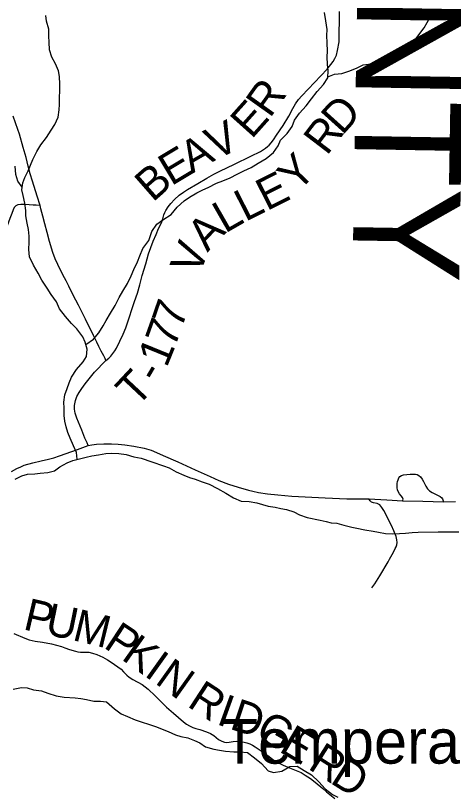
# Model space of a CAD drawing. Extents: x 0 to 34, y 0 to 22.
# Drawn here: x 26.05 to 26.826, y 17.051 to 18.434 of the extents above; entities that cross this region are included whole.
import ezdxf

# ---------------------------------------------------------------- set-up
doc = ezdxf.new("R2010")
doc.units = 0
for name, color, linetype in [('GM_X_County_Road', 7, 'Continuous'), ('GM_X_County_Text', 7, 'Continuous'), ('GM_X_Minor_River', 7, 'Continuous'), ('GM_X_Township_Road', 7, 'Continuous'), ('GM_X_Township_Road_Text', 7, 'Continuous'), ('GM_X_Unincorporated_Text', 7, 'Continuous')]:
    doc.layers.add(name, color=color, linetype=linetype)

msp = doc.modelspace()

# ---------------------------------------------------------------- linework, layer by layer
at = {"layer": 'GM_X_County_Road'}
msp.add_lwpolyline([(26.0424, 17.6262), (26.052, 17.6317), (26.0588, 17.6347), (26.0651, 17.6373), (26.0801, 17.6418), (26.0952, 17.6449), (26.1078, 17.6479), (26.1177, 17.6507), (26.1276, 17.6538), (26.1594, 17.665), (26.1783, 17.6721), (26.1851, 17.6732), (26.1934, 17.6744), (26.206, 17.6755), (26.2198, 17.675), (26.2317, 17.6744), (26.2435, 17.6734), (26.2594, 17.6713), (26.2779, 17.6678), (26.2902, 17.6639), (26.2998, 17.66), (26.3117, 17.6548), (26.3373, 17.6432), (26.3681, 17.6289), (26.3946, 17.6173), (26.4104, 17.6103), (26.4274, 17.6039), (26.4444, 17.5985), (26.4629, 17.5934), (26.4702, 17.5916), (26.4803, 17.5893), (26.4962, 17.5868), (26.5147, 17.5848), (26.5399, 17.5827), (26.5986, 17.5798), (26.6372, 17.5779), (26.6762, 17.5777), (26.7082, 17.5761), (26.7362, 17.5744), (26.7722, 17.5734), (26.8085, 17.5727), (26.8297, 17.5731)], dxfattribs=at)
at = {"layer": 'GM_X_Minor_River'}
for points in [[(26.286, 18.0353), (26.2913, 18.0514), (26.3002, 18.0644), (26.3107, 18.0721), (26.3254, 18.0818), (26.3362, 18.0948), (26.3485, 18.1056), (26.3583, 18.1122), (26.371, 18.1199), (26.3816, 18.125), (26.3913, 18.1293), (26.406, 18.137), (26.4173, 18.1414), (26.4301, 18.1468), (26.4429, 18.1531), (26.4545, 18.1589), (26.4673, 18.1647), (26.4797, 18.1725), (26.4939, 18.181), (26.5071, 18.1914), (26.5152, 18.2033), (26.5193, 18.2132), (26.5316, 18.2251), (26.5401, 18.2373), (26.5445, 18.2488), (26.5531, 18.261), (26.565, 18.274), (26.5743, 18.2867), (26.5844, 18.2993), (26.5959, 18.3116), (26.6034, 18.3238), (26.604, 18.3367), (26.6027, 18.3473), (26.6025, 18.361), (26.6028, 18.3709), (26.6022, 18.3856), (26.602, 18.3989), (26.6023, 18.4092), (26.6002, 18.4247), (26.5974, 18.4394)], [(26.6034, 18.3256), (26.6154, 18.3304), (26.6282, 18.3314), (26.6407, 18.3353), (26.6542, 18.3408), (26.6662, 18.347), (26.6802, 18.3487), (26.6923, 18.3492), (26.7048, 18.3517), (26.7171, 18.3594), (26.7288, 18.3683), (26.7412, 18.373), (26.7535, 18.3845), (26.7632, 18.3975), (26.7743, 18.4121), (26.7795, 18.4216), (26.7869, 18.4339), (26.797, 18.4438)], [(26.1589, 17.6479), (26.1579, 17.6601), (26.1525, 17.6718), (26.1464, 17.6855), (26.1426, 17.6953), (26.1392, 17.7056), (26.1373, 17.7154), (26.1361, 17.7253), (26.1357, 17.7386), (26.1353, 17.7488), (26.1372, 17.7621), (26.1409, 17.7732), (26.1447, 17.7834), (26.1489, 17.7933), (26.1579, 17.807), (26.1693, 17.8207), (26.1753, 17.8302), (26.1764, 17.8431), (26.173, 17.8556), (26.1688, 17.8651), (26.1585, 17.8791), (26.1486, 17.8886), (26.138, 17.9011), (26.1273, 17.9147), (26.1224, 17.9269), (26.1129, 17.9397), (26.1056, 17.9511), (26.0965, 17.9651), (26.0896, 17.9776), (26.0812, 17.992), (26.0744, 18.0064), (26.0732, 18.0197), (26.0736, 18.0326), (26.0735, 18.0429), (26.0727, 18.0547), (26.0704, 18.0664), (26.0681, 18.0793), (26.0681, 18.0888), (26.0658, 18.1017), (26.0631, 18.1154), (26.0608, 18.1252), (26.0627, 18.1378), (26.0661, 18.1473), (26.0721, 18.1591), (26.0763, 18.169), (26.0804, 18.1788), (26.0876, 18.1933), (26.0944, 18.2051), (26.1042, 18.218), (26.1126, 18.231), (26.119, 18.2412), (26.1254, 18.2542), (26.1269, 18.2667), (26.1276, 18.2762), (26.1276, 18.2887), (26.1279, 18.3009), (26.1283, 18.3127), (26.1275, 18.3263), (26.1256, 18.3358), (26.1206, 18.3483), (26.1138, 18.3601), (26.1099, 18.373), (26.1091, 18.3867), (26.1087, 18.3973), (26.1087, 18.4098), (26.1045, 18.4242), (26.1033, 18.4341)], [(26.0616, 18.1302), (26.0536, 18.1404), (26.0498, 18.1525), (26.049, 18.167)], [(26.1741, 17.8515), (26.1878, 17.8606), (26.1972, 17.8717), (26.2048, 17.8842), (26.2105, 17.8937), (26.218, 17.9067), (26.226, 17.9204), (26.2335, 17.9344), (26.24, 17.9455), (26.2479, 17.9595), (26.2547, 17.9728), (26.2596, 17.9839), (26.266, 17.9976), (26.2702, 18.0086), (26.2755, 18.0211), (26.286, 18.0353)], [(26.0491, 17.6127), (26.0608, 17.6184), (26.0707, 17.6218), (26.0836, 17.6223), (26.0931, 17.6231), (26.1067, 17.6242), (26.1185, 17.6277), (26.128, 17.6345), (26.1412, 17.6414), (26.1511, 17.6456), (26.1606, 17.6483), (26.175, 17.6514), (26.1848, 17.6537), (26.197, 17.6556), (26.2099, 17.658), (26.2205, 17.6588), (26.2326, 17.658), (26.2455, 17.6562), (26.2592, 17.6524), (26.2725, 17.6498), (26.2914, 17.6431)], [(26.2914, 17.6431), (26.3123, 17.6365), (26.3222, 17.6325), (26.3344, 17.6254), (26.3481, 17.6196), (26.3584, 17.6159), (26.3679, 17.6126), (26.3804, 17.6078), (26.3933, 17.6038), (26.4078, 17.5964), (26.4226, 17.5879), (26.4363, 17.5797), (26.4497, 17.5738), (26.464, 17.5732), (26.4773, 17.5708), (26.4879, 17.5675), (26.4978, 17.565), (26.5103, 17.5628), (26.5202, 17.5607), (26.5304, 17.5589), (26.5433, 17.5549), (26.5532, 17.5497), (26.5669, 17.5446), (26.5896, 17.5403), (26.6003, 17.5374), (26.6097, 17.5353), (26.6196, 17.5346), (26.6321, 17.5314), (26.6458, 17.5274), (26.6552, 17.5256), (26.6693, 17.5231), (26.6837, 17.5203), (26.6935, 17.5185), (26.706, 17.5164), (26.7189, 17.5158), (26.7306, 17.5163), (26.7412, 17.5172), (26.7529, 17.5181), (26.7639, 17.519), (26.7994, 17.5195), (26.8108, 17.5192), (26.8255, 17.5194), (26.8361, 17.5196)], [(26.0454, 17.2406), (26.0602, 17.2433), (26.0704, 17.243), (26.0814, 17.2396), (26.0958, 17.2374), (26.1068, 17.2336), (26.1217, 17.2287), (26.1361, 17.2265), (26.1551, 17.225), (26.1653, 17.2239), (26.1755, 17.2221), (26.1885, 17.2195), (26.2002, 17.2195), (26.2108, 17.218), (26.2249, 17.2055), (26.2371, 17.1968), (26.2481, 17.1919), (26.2618, 17.1863), (26.2979, 17.1743)], [(26.2979, 17.1743), (26.32, 17.1658), (26.3333, 17.1599), (26.3428, 17.157), (26.3554, 17.1541), (26.3668, 17.1497), (26.3763, 17.1457), (26.3866, 17.1386), (26.4014, 17.1342), (26.4116, 17.1325), (26.4222, 17.1307), (26.4366, 17.1294), (26.4476, 17.1295), (26.4612, 17.1286), (26.4734, 17.1192), (26.486, 17.1088), (26.4975, 17.0957), (26.5074, 17.0927), (26.5217, 17.0956), (26.536, 17.1033), (26.5489, 17.1039), (26.5618, 17.0968), (26.5748, 17.0887), (26.5874, 17.0763), (26.5989, 17.0643), (26.6115, 17.0539), (26.621, 17.0494)]]:
    msp.add_lwpolyline(points, dxfattribs=at)
at = {"layer": 'GM_X_Township_Road'}
for points in [[(26.1783, 17.6721), (26.1765, 17.6772), (26.1725, 17.6855), (26.167, 17.6994), (26.1611, 17.7137), (26.1581, 17.7209), (26.1554, 17.7298), (26.1543, 17.7365), (26.1541, 17.743), (26.1557, 17.752), (26.1584, 17.7589), (26.1626, 17.7661), (26.1671, 17.7732), (26.1732, 17.7814), (26.1898, 17.8021), (26.2095, 17.8227), (26.215, 17.8272), (26.2187, 17.8306), (26.2224, 17.8351), (26.2254, 17.8398), (26.2284, 17.845), (26.2348, 17.8574), (26.2407, 17.8698), (26.2454, 17.8809), (26.2507, 17.8968), (26.2572, 17.9166), (26.2607, 17.9277), (26.266, 17.9422), (26.2703, 17.957), (26.2742, 17.9733), (26.2804, 17.9939), (26.2857, 18.0116), (26.2939, 18.0343), (26.2988, 18.0462), (26.3034, 18.0568), (26.3083, 18.0667), (26.3107, 18.0738), (26.3125, 18.081), (26.3144, 18.0851), (26.316, 18.0885), (26.3203, 18.0954), (26.325, 18.1012), (26.3313, 18.1081), (26.3397, 18.1158), (26.3473, 18.121), (26.3546, 18.1259), (26.3729, 18.1366), (26.3886, 18.1461), (26.4014, 18.1531), (26.4122, 18.1585), (26.4377, 18.1706), (26.4668, 18.1849), (26.484, 18.1934), (26.4928, 18.199), (26.4966, 18.2018), (26.4996, 18.2046), (26.5032, 18.2085), (26.5072, 18.2137), (26.5127, 18.2222), (26.524, 18.2394), (26.5346, 18.2558), (26.5415, 18.2695), (26.546, 18.2774), (26.5515, 18.2851), (26.5576, 18.2917), (26.6022, 18.3392), (26.609, 18.3473), (26.613, 18.3529), (26.6159, 18.3577), (26.6186, 18.364), (26.6209, 18.3723), (26.6236, 18.3872), (26.6243, 18.4411)], [(26.2095, 17.8227), (26.2083, 17.8267), (26.206, 17.8313), (26.2015, 17.8397), (26.1972, 17.8474), (26.1935, 17.8555), (26.1909, 17.8614), (26.1879, 17.8673), (26.1854, 17.8725), (26.1815, 17.8804), (26.1738, 17.8964), (26.1679, 17.908), (26.1614, 17.9207), (26.152, 17.9385), (26.1441, 17.9543), (26.1391, 17.9638), (26.1365, 17.9691), (26.1292, 17.9827), (26.1201, 18.0029), (26.1158, 18.0144), (26.11, 18.0339), (26.1054, 18.0496), (26.1013, 18.0648), (26.0979, 18.0788), (26.0946, 18.0917), (26.0931, 18.0975), (26.0879, 18.114), (26.0796, 18.1406), (26.0756, 18.1535), (26.0718, 18.167), (26.0682, 18.1825), (26.0631, 18.2005), (26.0567, 18.2239), (26.0538, 18.2323), (26.0456, 18.2559)], [(26.0931, 18.0975), (26.0863, 18.0982), (26.081, 18.0983), (26.0668, 18.099), (26.0591, 18.0991), (26.0539, 18.0984), (26.0498, 18.0967), (26.0474, 18.0938), (26.0454, 18.0898), (26.0431, 18.0832), (26.0396, 18.0745), (26.0347, 18.0613), (26.0298, 18.0502), (26.0262, 18.0437), (26.0228, 18.0387), (26.0192, 18.0349), (26.0148, 18.031), (26.0098, 18.0279), (25.9981, 18.0232)], [(26.7362, 17.5744), (26.737, 17.5774), (26.7362, 17.5799), (26.7338, 17.5834), (26.7307, 17.5864), (26.728, 17.5908), (26.7272, 17.5935), (26.7265, 17.5973), (26.7264, 17.6007), (26.7266, 17.6047), (26.7272, 17.6083), (26.728, 17.6117), (26.7294, 17.6152), (26.7314, 17.6173), (26.7341, 17.6193), (26.7377, 17.6206), (26.7498, 17.6213), (26.7588, 17.6215), (26.7619, 17.6208), (26.765, 17.6193), (26.7679, 17.6166), (26.7709, 17.6129), (26.7734, 17.6087), (26.7775, 17.6005), (26.7804, 17.5956), (26.7839, 17.5922), (26.7884, 17.5889), (26.793, 17.5864), (26.7991, 17.5838), (26.8029, 17.5819), (26.8056, 17.5797), (26.807, 17.5776), (26.8085, 17.5727)], [(26.6816, 17.4199), (26.687, 17.4274), (26.696, 17.4416), (26.7103, 17.4664), (26.713, 17.471), (26.72, 17.4833), (26.723, 17.4898), (26.7246, 17.4928), (26.7259, 17.4966), (26.7264, 17.5004), (26.7261, 17.5052), (26.7247, 17.5111), (26.7207, 17.5212), (26.7166, 17.5308), (26.7029, 17.557), (26.6995, 17.5625), (26.6976, 17.5651), (26.6955, 17.5669), (26.6933, 17.5685), (26.6908, 17.5694), (26.6844, 17.5708), (26.6807, 17.5718), (26.6783, 17.574), (26.6762, 17.5777)], [(26.0464, 17.3392), (26.066, 17.331), (26.0739, 17.3282), (26.0844, 17.3255), (26.0972, 17.3236), (26.1133, 17.3208), (26.1221, 17.3187), (26.1311, 17.3163), (26.1372, 17.3141), (26.1454, 17.3111), (26.1562, 17.3079), (26.1602, 17.3069), (26.165, 17.3064), (26.1796, 17.306), (26.186, 17.3045), (26.1936, 17.3022), (26.2043, 17.2972), (26.2124, 17.2927), (26.2191, 17.2885), (26.2249, 17.2846), (26.2313, 17.2801), (26.2367, 17.2759), (26.241, 17.2713), (26.247, 17.2652), (26.2511, 17.262), (26.2574, 17.2579), (26.2744, 17.2489), (26.2848, 17.2404), (26.2973, 17.2285), (26.3171, 17.2088), (26.3298, 17.1978), (26.3472, 17.1826), (26.3529, 17.1786), (26.3583, 17.1755), (26.3638, 17.1729), (26.3695, 17.171), (26.3762, 17.169), (26.3882, 17.1648), (26.3951, 17.1619), (26.4015, 17.1584), (26.4057, 17.1549), (26.4095, 17.1517), (26.4152, 17.1485), (26.4204, 17.1466), (26.424, 17.1463), (26.4287, 17.1466), (26.4357, 17.1477), (26.4422, 17.1483), (26.4485, 17.1481), (26.4551, 17.147), (26.4599, 17.1457), (26.4649, 17.1436), (26.4699, 17.1411), (26.4745, 17.1386), (26.4784, 17.1363), (26.4851, 17.1314), (26.4992, 17.1212), (26.5062, 17.1159), (26.5148, 17.1104), (26.524, 17.1057), (26.5355, 17.1012), (26.556, 17.0928), (26.5634, 17.0883), (26.5725, 17.0822), (26.5812, 17.0758), (26.5948, 17.0644), (26.6014, 17.0588), (26.6098, 17.0519), (26.6162, 17.047)]]:
    msp.add_lwpolyline(points, dxfattribs=at)

# ---------------------------------------------------------------- texts
at = {"layer": 'GM_X_County_Text'}
msp.add_text('NOBLE COUNTY', height=0.189394, rotation=269.0214, dxfattribs=at).set_placement((26.6811, 19.9608))
at = {"layer": 'GM_X_Township_Road_Text'}
for s, rotation, p in [('R', 54.6032, (26.5008, 18.2509)), ('D', 48.0331, (26.6291, 18.2205)), ('E', 48.2074, (26.4682, 18.2138)), ('V', 26.236, (26.4045, 18.1774)), ('R', 52.6508, (26.6016, 18.1844)), ('A', 29.781, (26.3619, 18.153)), ('E', 30.9101, (26.3257, 18.1313)), ('Y', 46.3957, (26.5501, 18.119)), ('B', 41.2439, (26.2928, 18.1021)), ('E', 26.6455, (26.495, 18.0872)), ('L', 26.8046, (26.4571, 18.0681)), ('L', 29.8826, (26.421, 18.0473)), ('A', 46.2726, (26.3898, 18.0138)), ('V', 69.5753, (26.3756, 17.9721)), ('7', 71.0166, (26.3437, 17.8774)), ('7', 70.3643, (26.3317, 17.8438)), ('1', 67.823, (26.3175, 17.8088)), ('T', 46.8124, (26.2644, 17.7387)), ('-', 59.6296, (26.3018, 17.7807)), ('P', 346.8903, (26.0613, 17.347)), ('U', 348.4336, (26.1002, 17.3379)), ('M', 346.2188, (26.1486, 17.328)), ('P', 326.4694, (26.2038, 17.3154)), ('K', 324.5284, (26.2353, 17.2945)), ('I', 324.4714, (26.276, 17.2655)), ('N', 324.4739, (26.295, 17.252)), ('R', 326.8846, (26.3521, 17.2113)), ('I', 340.1701, (26.4041, 17.1794)), ('D', 341.4655, (26.4273, 17.171)), ('G', 329.6872, (26.4719, 17.1564)), ('E', 329.2222, (26.515, 17.1312)), ('R', 327.6479, (26.5662, 17.1007)), ('D', 327.5204, (26.6056, 17.0757))]:
    msp.add_text(s, height=0.0568, rotation=rotation, dxfattribs=at).set_placement(p)
at = {"layer": 'GM_X_Unincorporated_Text'}
msp.add_text('Temperanceville', height=0.078977, rotation=0, dxfattribs=at).set_placement((26.4154, 17.1087))

doc.saveas('drawing.dxf')
